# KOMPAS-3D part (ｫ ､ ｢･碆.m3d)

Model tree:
1. Эскиз:1
2. Операция выдавливания:1
     Расстояние 1 = 20
3. Эскиз:2
4. Операция выдавливания:2
     Расстояние 1 = 400
5. Эскиз:3
6. Вырезать элемент выдавливания:1
     Расстояние 1 = 70
7. Эскиз:4
8. Вырезать элемент выдавливания:2
     Расстояние 1 = 2
9. Эскиз:5
10. Эскиз:11
11. Вырезать элемент выдавливания:7
     Расстояние 1 = 30
12. Операция выдавливания:3
     Расстояние 1 = 16.96
13. Эскиз:13
14. Вырезать элемент выдавливания:9
     Расстояние 1 = 70
